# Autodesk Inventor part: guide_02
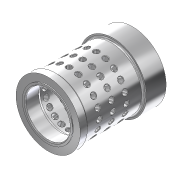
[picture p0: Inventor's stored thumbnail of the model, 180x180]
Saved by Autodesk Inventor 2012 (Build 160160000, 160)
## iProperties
Created: 2002-03
Part Number: guide_02
Document SubType Name: Modeling
Designer: Lieven Grauls
Stock Number: guide_02
Project: Valve Techcamp 2008
Density: 1 g/cm^3
Mass: 121.014 g
Surface Area: 393.413 cm^2
Volume: 121.014 cm^3
Material: Default
Company: Autodesk
Control State: 0
Master: False
Checked Out: False
Shininess: 59.0
Length Units: 11269
Angle Units: 11279
Time Units: 11290
Mass Units: 11283
Length Display Precision: 3
Angle Display Precision: 2
Density: 0.0
Volumn: 0.0
Area: 0.0
PropertySet Name: Model Information
Author: Lieven Grauls
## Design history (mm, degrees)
sketch "Sketch1"
  geometry: L1 (0, 113.1)-(0, -18.85) reference; L2 (22, 0)-(39.5, 0) reference; L3 (24.5, 0)-(24.5, 14.855); L4 (24.5, 14.855)-(26.5, 18.25); L5 (26.5, 18.25)-(26.5, 94.25); L6 (26.5, 94.25)-(37, 94.25); L7 (37, 94.25)-(37, 72.612); L8 (37, 72.612)-(33.467, 72.612); L9 (35.468, 0.9)-(27.75, 0.9); L10 (27.75, 0.9)-(27.75, 0); L11 (35.468, 8.821)-(33.468, 8.821); L12 (33.468, 8.821)-(33.467, 72.612); L13 (35.468, 8.821)-(35.468, 0.9)
  constraints: 22 end point, 8 perpendicular, 2 parallel, 2 point on line
  dimensions: "d3" = 0.9 distance from line of L10.end L9; "d6" = 21.638 distance of L7.end L6.end; "d11" = 30.5 deg angle of L5 L4; "d12" = 76 vertical distance of L4.end L6.end; "d83" = 53 diameter of L5.end L1; "d85" = 74 diameter of L6.end L1; "d86" = 49 diameter of L3 L1; "d87" = 55.5 diameter of L10.end L1; "d97" = 93.35 distance between parallel lines of L6 L9; "d99" = 2 distance of L11.start L11.end; "d100" = 70.935 diameter of L13 L1; "d101" = 7.921 distance of L11.start L9.start
revolve "Revolution1" sketch "Sketch1" stored, may be unused: angle "d13" = 90 deg
workplane "Work Plane1"
sketch "Sketch2"
  geometry: L1 (0, 29.669)-(0, -102.281) reference; L2 (-27.75, -83.431)-(27.75, -83.431) reference; 3 further points
  constraints: 3 point on line
  dimensions: "d21" = 24 distance from line of point (0, -59.431) L2; "d104" = 12.5 distance of point (0, -46.931) point (0, -59.431); "d105" = 12.5 distance of point (0, -34.431) point (0, -46.931) (= d104)
hole "Hole1" sketch "Sketch2" diameter "d28" = 8; stored, may be unused: countersink angle "d32" = 82 deg, drill point angle "d34" = 118 deg; dims "d29" = 6, "d30" = 4, "d31" = 2, "d33" = 20
fillet "Fillet4" dims "d103" = 1
pattern_circular "Circular Pattern2" dims angle "d54" = 360 deg
fillet "Fillet2" dims "d98" = 2
fillet "Fillet3" dims "d102" = 1
node "Volumenkörper1"
node "Volumenkörpern"
node "Oberflächenkörpern"
